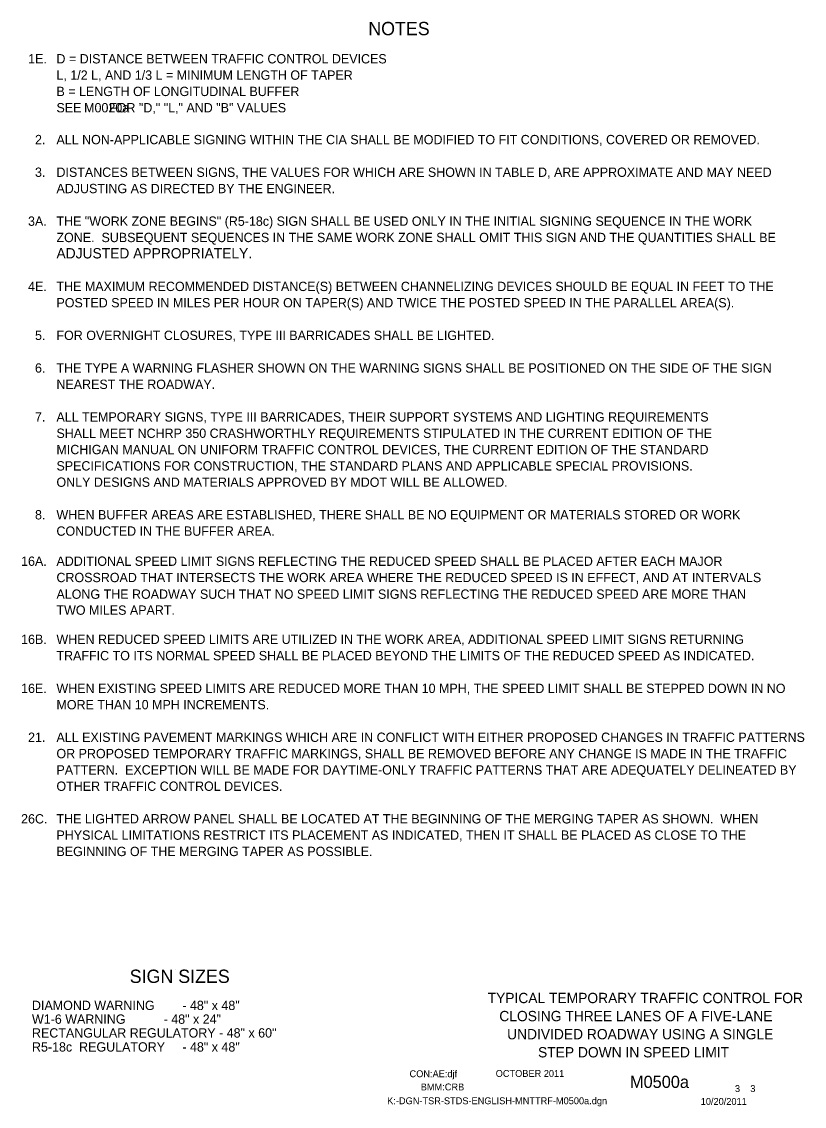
# Model space of a CAD drawing. Extents: x 16738 to 19504, y 5697 to 6916.
# Drawn here: x 18799 to 19504, y 5932 to 6909 of the extents above; entities that cross this region are included whole.
import ezdxf

# ---------------------------------------------------------------- set-up
doc = ezdxf.new("R2010")
doc.units = 0
for name, color, linetype in [('BORDER', 7, 'Continuous'), ('BORDER_SIGNAL_WO', 7, 'Continuous'), ('TYPICAL_TEXT_DIMEN_PR', 7, 'Continuous')]:
    doc.layers.add(name, color=color, linetype=linetype)

msp = doc.modelspace()

# ---------------------------------------------------------------- linework, layer by layer
at = {"layer": 'BORDER'}
msp.add_line((18938.25, 6055), (18938.25, 6055), dxfattribs=at)

# ---------------------------------------------------------------- texts
for s, p in [('TYPICAL TEMPORARY TRAFFIC CONTROL FOR', (19219.04, 6024.8)), ('CLOSING THREE LANES OF A FIVE-LANE', (19229.56, 6008.5)), ('UNDIVIDED ROADWAY USING A SINGLE', (19236.56, 5992.2)), ('STEP DOWN IN SPEED LIMIT', (19264.42, 5975.9))]:
    msp.add_text(s, height=9.3, dxfattribs=at).set_placement(p)
at = {"layer": 'BORDER_SIGNAL_WO'}
for s, height, p in [('CON:AE:djf', 6.2, (19148.69, 5958.06)), ('    OCTOBER 2011    ', 6.2, (19217.08, 5958.34)), ('BMM:CRB   ', 6.2, (19158.81, 5946.17)), ('    M0500a   ', 11, (19330.86, 5948.38)), (' 3    3 ', 6.2, (19439.45, 5944.7)), ('K:-DGN-TSR-STDS-ENGLISH-MNTTRF-M0500a.dgn        ', 6.2, (19128.55, 5933.71)), ('10/20/2011    ', 6.2, (19410.93, 5933.13))]:
    msp.add_text(s, height=height, dxfattribs=at).set_placement(p)
at = {"layer": 'TYPICAL_TEXT_DIMEN_PR'}
for s, height, p in [('NOTES', 12, (19111.55, 6897)), ('1E.', 8.4, (18805.19, 6871.56)), ('D = DISTANCE BETWEEN TRAFFIC CONTROL DEVICES', 8.4, (18830.7, 6871.56)), ('L, 1/2 L, AND 1/3 L = MINIMUM LENGTH OF TAPER', 8.4, (18830.7, 6856.86)), ('B = LENGTH OF LONGITUDINAL BUFFER', 8.4, (18830.7, 6842.16)), ('SEE        FOR "D," "L," AND "B" VALUES', 8.4, (18830.7, 6827.46)), ('M0020a', 8.4, (18855.62, 6827.46)), ('2.', 8.4, (18811.39, 6798.75)), ('ALL NON-APPLICABLE SIGNING WITHIN THE CIA SHALL BE MODIFIED TO FIT CONDITIONS, COVERED OR REMOVED.', 8.4, (18830.7, 6798.75)), ('3.', 8.4, (18811.39, 6769.35)), ('DISTANCES BETWEEN SIGNS, THE VALUES FOR WHICH ARE SHOWN IN TABLE D, ARE APPROXIMATE AND MAY NEED', 8.4, (18830.7, 6769.35)), ('ADJUSTING AS DIRECTED BY THE ENGINEER.', 8.4, (18830.7, 6754.65)), ('THE "WORK ZONE BEGINS" (R5-18c) SIGN SHALL BE USED ONLY IN THE INITIAL SIGNING SEQUENCE IN THE WORK', 8.4, (18830.7, 6725.25)), ('3A.', 8.4, (18805.09, 6725.25)), ('ZONE.  SUBSEQUENT SEQUENCES IN THE SAME WORK ZONE SHALL OMIT THIS SIGN AND THE QUANTITIES SHALL BE', 8.4, (18830.7, 6710.55)), ('ADJUSTED APPROPRIATELY.', 9.3, (18830.7, 6695.85)), ('THE MAXIMUM RECOMMENDED DISTANCE(S) BETWEEN CHANNELIZING DEVICES SHOULD BE EQUAL IN FEET TO THE', 8.4, (18830.7, 6666.45)), ('4E.', 8.4, (18805.13, 6666.45)), ('POSTED SPEED IN MILES PER HOUR ON TAPER(S) AND TWICE THE POSTED SPEED IN THE PARALLEL AREA(S).', 8.4, (18830.7, 6651.75)), ('5.', 8.4, (18811.39, 6622.35)), ('FOR OVERNIGHT CLOSURES, TYPE III BARRICADES SHALL BE LIGHTED.', 8.4, (18830.7, 6622.35)), ('6.', 8.4, (18811.34, 6592.95)), ('THE TYPE A WARNING FLASHER SHOWN ON THE WARNING SIGNS SHALL BE POSITIONED ON THE SIDE OF THE SIGN', 8.4, (18830.7, 6592.95)), ('NEAREST THE ROADWAY.', 8.4, (18830.7, 6578.25)), ('7.', 8.4, (18811.34, 6548.83)), ('ALL TEMPORARY SIGNS, TYPE III BARRICADES, THEIR SUPPORT SYSTEMS AND LIGHTING REQUIREMENTS', 8.4, (18830.7, 6548.85)), ('SHALL MEET NCHRP 350 CRASHWORTHLY REQUIREMENTS STIPULATED IN THE CURRENT EDITION OF THE', 8.4, (18830.7, 6534.15)), ('MICHIGAN MANUAL ON UNIFORM TRAFFIC CONTROL DEVICES, THE CURRENT EDITION OF THE STANDARD', 8.4, (18830.7, 6519.45)), ('SPECIFICATIONS FOR CONSTRUCTION, THE STANDARD PLANS AND APPLICABLE SPECIAL PROVISIONS.', 8.4, (18830.7, 6504.75)), ('ONLY DESIGNS AND MATERIALS APPROVED BY MDOT WILL BE ALLOWED.', 8.4, (18830.7, 6490.05)), ('8.', 8.4, (18811.39, 6460.66)), ('WHEN BUFFER AREAS ARE ESTABLISHED, THERE SHALL BE NO EQUIPMENT OR MATERIALS STORED OR WORK     ', 8.4, (18830.7, 6460.66)), ('CONDUCTED IN THE BUFFER AREA.', 8.4, (18830.7, 6445.96)), ('16A.', 8.4, (18798.84, 6418.85)), ('ADDITIONAL SPEED LIMIT SIGNS REFLECTING THE REDUCED SPEED SHALL BE PLACED AFTER EACH MAJOR', 8.4, (18830.7, 6418.85)), ('CROSSROAD THAT INTERSECTS THE WORK AREA WHERE THE REDUCED SPEED IS IN EFFECT, AND AT INTERVALS', 8.4, (18830.7, 6404.15)), ('ALONG THE ROADWAY SUCH THAT NO SPEED LIMIT SIGNS REFLECTING THE REDUCED SPEED ARE MORE THAN', 8.4, (18830.7, 6389.15)), ('TWO MILES APART.', 8.4, (18830.7, 6374.75)), ('16B.', 8.4, (18798.84, 6348.4)), ('WHEN REDUCED SPEED LIMITS ARE UTILIZED IN THE WORK AREA, ADDITIONAL SPEED LIMIT SIGNS RETURNING', 8.4, (18830.7, 6348.46)), ('TRAFFIC TO ITS NORMAL SPEED SHALL BE PLACED BEYOND THE LIMITS OF THE REDUCED SPEED AS INDICATED.', 8.4, (18830.7, 6333.76)), ('16E.', 8.4, (18798.84, 6304.26)), ('WHEN EXISTING SPEED LIMITS ARE REDUCED MORE THAN 10 MPH, THE SPEED LIMIT SHALL BE STEPPED DOWN IN NO', 8.4, (18830.7, 6304.26)), ('MORE THAN 10 MPH INCREMENTS.', 8.4, (18830.7, 6289.56)), ('21.', 8.4, (18805.14, 6260.2)), ('ALL EXISTING PAVEMENT MARKINGS WHICH ARE IN CONFLICT WITH EITHER PROPOSED CHANGES IN TRAFFIC PATTERNS', 8.4, (18830.7, 6260.2)), ('OR PROPOSED TEMPORARY TRAFFIC MARKINGS, SHALL BE REMOVED BEFORE ANY CHANGE IS MADE IN THE TRAFFIC', 8.4, (18830.7, 6245.5)), ('PATTERN.  EXCEPTION WILL BE MADE FOR DAYTIME-ONLY TRAFFIC PATTERNS THAT ARE ADEQUATELY DELINEATED BY', 8.4, (18830.7, 6230.8)), ('OTHER TRAFFIC CONTROL DEVICES.', 8.4, (18830.7, 6216.1)), ('26C.', 8.4, (18798.83, 6186.7)), ('THE LIGHTED ARROW PANEL SHALL BE LOCATED AT THE BEGINNING OF THE MERGING TAPER AS SHOWN.  WHEN', 8.4, (18830.7, 6186.7)), ('PHYSICAL LIMITATIONS RESTRICT ITS PLACEMENT AS INDICATED, THEN IT SHALL BE PLACED AS CLOSE TO THE', 8.4, (18830.7, 6172)), ('BEGINNING OF THE MERGING TAPER AS POSSIBLE.', 8.4, (18830.7, 6157.3)), ('SIGN SIZES', 12, (18896.69, 6043)), ('DIAMOND WARNING        - 48" x 48"', 8.4, (18808.65, 6018.6)), ('W1-6 WARNING           - 48" x 24"', 8.4, (18808.65, 6006.2)), ('RECTANGULAR REGULATORY - 48" x 60"', 8.4, (18808.65, 5993.8)), ('R5-18c  REGULATORY     - 48" x 48"', 8.4, (18808.65, 5981.15))]:
    msp.add_text(s, height=height, dxfattribs=at).set_placement(p)

doc.saveas('drawing.dxf')
